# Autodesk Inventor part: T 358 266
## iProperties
Created: 2006-03
Part Number: T 358 266
Material: 1.0718.07
Document SubType Name: Modeling
Designer: I.Baliuc
Description: Druckring
Density: 7.84 g/cm^3
Title: Druckring
Company: Mayer & Müller AG Schaltgeräte
HalbzeugNorm: DIN 671
Zweck: Schaltrohr Trenner
Abmessung: Rd. St. 60
Author: T.Messerschmitt
Revision Number: 358266
Keywords: 266470
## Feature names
1. Extrusion2
2. Fase1 [Chamfer]
3. Rundung3 [Fillet]
